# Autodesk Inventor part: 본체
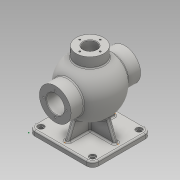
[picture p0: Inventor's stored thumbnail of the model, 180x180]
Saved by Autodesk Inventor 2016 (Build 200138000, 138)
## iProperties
Created: 2017-01
Part Number: 본체
Material: 일반
Document SubType Name: Modeling
Designer: Administrator
Density: 1 g/cm^3
Appearance: 기본값
Author: Administrator
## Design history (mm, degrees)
sketch "스케치1"
  geometry: L1 (0, 0)-(125, 0); L2 (125, 0)-(125, 115); L3 (125, 115)-(0, 115); L4 (0, 115)-(0, 0)
  constraints: 8 end point, 2 parallel, 1 horizontal, 1 perpendicular
  dimensions: "d0" = 125 distance between parallel lines of L2 L4; "d1" = 115 distance between parallel lines of L1 L3
extrude "돌출1" new body sketch "스케치1" distance "d2" = 10; taper "d3" = 0 deg
fillet "모깎기1" dims "d4" = 12
sketch "스케치2"
  geometry: A1 r 12 centre (12, 103) between (12, 115) and (0, 103) reference; A2 r 12 centre (113, 103) between (125, 103) and (113, 115) reference; A3 r 12 centre (113, 12) between (113, 0) and (125, 12) reference; A4 r 12 centre (12, 12) between (0, 12) and (12, 0) reference; 5 further points
  constraints: 4 coincident
hole "구멍1" sketch "스케치2" at (12, 103), (113, 103), (113, 12), (12, 12) diameter "d5" = 8; stored, may be unused: countersink angle "d9" = 90 deg, drill point angle "d11" = 118 deg; dims "d6" = 6, "d7" = 12, "d8" = 3, "d10" = 8
node "작업 평면2"
sketch "스케치5"
  geometry: L1 (0, 91)-(0, 0) reference; L2 (0, 45.5)-(-120.31, 45.5); L3 (-85, -22.5)-(-85, 113.5); L4 (-85, -22.5)-(-116, -22.5); L5 (-116, -22.5)-(-116, 2.512); L6 (-116, 88.488)-(-116, 113.5); L7 (-116, 113.5)-(-85, 113.5); A1 r 53 centre (-85, 45.5) between (-116, 88.488) and (-116, 2.512); 1 further point
  constraints: 12 end point, 2 horizontal, 2 midpoint, 2 perpendicular, 2 point on circle, 2 vertical, 1 centre point, 1 point on line
  dimensions: "d31" = 106 diameter of A1; "d32" = 85 distance between parallel lines of L1 L3; "d33" = 31 distance between parallel lines of L3 L5; "d34" = 31 distance between parallel lines of L3 L6; "d35" = 136 distance between parallel lines of L7 L4; "d36" = 68 distance between parallel lines of L4 L2
revolve "회전2" sketch "스케치5" stored, may be unused: angle "d37" = 90 deg
sketch "스케치6"
  geometry: L1 (-54, -22.5)-(-116, -22.5) reference; L2 (-85, -22.5)-(-85, 113.5); L3 (-54, 113.5)-(-116, 113.5) reference; L4 (-85, -22.5)-(-102.5, -22.5); L5 (-102.5, -22.5)-(-102.5, 6.222); L6 (-85, 113.5)-(-102.5, 113.5); L7 (-102.5, 95.75)-(-103.5, 95.75); L8 (-103.5, 95.75)-(-103.5, 97.5); L9 (-103.5, 97.5)-(-102.5, 97.5); L10 (-102.5, 84.778)-(-102.5, 95.75); L11 (-102.5, 97.5)-(-102.5, 113.5); A1 r 43 centre (-85, 45.5) between (-102.5, 84.778) and (-102.5, 6.222); 1 further point
  constraints: 18 end point, 3 midpoint, 3 perpendicular, 3 point on line, 2 parallel, 2 point on circle, 1 centre point, 1 vertical
  dimensions: "d38" = 86 diameter of A1; "d39" = 17.5 distance between parallel lines of L2 L5; "d40" = 17.5 distance between parallel lines of L2 L10; "d41" = 16 distance between parallel lines of L3 L9; "d42" = 1.75 distance between parallel lines of L7 L9; "d43" = 18.5 distance between parallel lines of L2 L8
revolve "회전3" sketch "스케치6" stored, may be unused: angle "d44" = 90 deg
sketch "스케치7"
  geometry: C1 r 17.5 at (0, 0) reference; A1 r 22.5 centre (0, 0) between (0, 22.5) and (22.5, 0); 3 further points
  constraints: 4 point on circle, 1 centre point, 1 coincident
  dimensions: "d45" = 45 diameter of A1
hole "구멍2" sketch "스케치7" at (0, 22.5), (22.5, 0), (0, -22.5), (-22.5, 0) diameter "d46" = 3.242; stored, may be unused: countersink angle "d50" = 90 deg, drill point angle "d52" = 118 deg; dims "d47" = 12, "d48" = 12, "d49" = 3, "d51" = 15
sketch "스케치8"
  geometry: C1 r 17.5 at (0, 0) reference; A1 r 24 centre (0, 0) between (-24, 0) and (0, -24); 3 further points
  constraints: 4 point on circle, 1 centre point, 1 coincident
  dimensions: "d53" = 48 diameter of A1
hole "구멍3" sketch "스케치8" at (-24, 0), (0, -24), (24, 0), (0, 24) diameter "d54" = 3.242; stored, may be unused: countersink angle "d58" = 90 deg, drill point angle "d60" = 118 deg; dims "d55" = 16, "d56" = 12, "d57" = 3, "d59" = 19
node "작업 평면3"
sketch "스케치9"
  geometry: L1 (-31.5, -10.5)-(-93.5, -10.5) reference; L2 (-62.5, -10.5)-(-62.5, 125.5); L3 (-31.5, 125.5)-(-93.5, 125.5) reference; L4 (0, 103)-(0, 12) reference; L5 (0, 57.5)-(-125, 57.5); L6 (-125, 12)-(-125, 103) reference; C1 r 27 at (-62.5, 57.5); 1 further point
  constraints: 4 end point, 4 midpoint, 1 centre point
  dimensions: "d62" = 54 diameter of C1; "d63" = 0 distance from line of C1.centre L2; "d64" = 0 distance from line of L5 C1.centre
extrude "돌출2" join sketch "스케치9" stored distance "d65" = 10; taper "d66" = 0 deg
sketch "스케치10"
  geometry: C1 r 27 at (0, 0) reference; C2 r 13 at (0, 0); 1 further point
  constraints: 1 centre point, 1 coincident
  dimensions: "d67" = 26 diameter of C2
extrude "돌출3" cut sketch "스케치10" distance "d68" = 60.25; taper "d69" = 0 deg
sketch "스케치11"
  geometry: C1 r 13 at (0, 0) reference; A1 r 20 centre (0, 0) between (0, 20) and (20, 0); 3 further points
  constraints: 4 point on circle, 1 centre point, 1 coincident
  dimensions: "d70" = 40 diameter of A1
hole "구멍4" sketch "스케치11" at (0, 20), (20, 0), (0, -20), (-20, 0) diameter "d71" = 3.242; stored, may be unused: countersink angle "d75" = 90 deg, drill point angle "d77" = 118 deg; dims "d72" = 9, "d73" = 12, "d74" = 3, "d76" = 11
sketch "스케치12"
  geometry: L1 (-10, 91)-(-10, 0) reference; L2 (-85.332, 45.09)-(-10, 45.5); L3 (-44.107, 11.78)-(-10, -2); L4 (-44.613, 79.016)-(-10, 93); L5 (-10, -12)-(-10, 0) reference; L6 (-10, 91)-(-10, 103) reference; L7 (-10, -12)-(-10, 103); L8 (-10, 103)-(0, 103) reference; L9 (0, -12)-(-10, -12) reference; L10 (-10, -2)-(-10, 93); A1 r 53 centre (-85.332, 45.09) between (-44.107, 11.78) and (-44.613, 79.016); A2 r 53 centre (-85.332, 45.09) between (-44.107, 11.78) and (-44.613, 79.016)
  constraints: 10 end point, 4 point on circle, 2 centre point, 2 coincident, 2 point on line, 1 collinear, 1 midpoint, 1 vertical
  dimensions: "d79" = 10 distance from line of L8 L4.end; "d80" = 10 distance from line of L9 L3.end; "d81" = 112 deg angle of L5 L3; "d82" = 112 deg angle of L4 L6; "d84" = 106 diameter of A2
extrude "돌출4" join sketch "스케치12" stored distance "d85" = 8; taper "d86" = 0 deg
node "작업 평면4"
sketch "스케치13" dims "d88" = 106
  geometry: L1 (13.121, 47.426)-(-2, 10); L2 (0, 10)-(0, 0) reference; L3 (95, 10)-(107, 10) reference; L4 (0, 10)-(107, 10); L5 (-12, 0)-(-12, 10) reference; L6 (-12, 10)-(0, 10) reference; C1 r 17.5 at (50.5, 85) reference; 1 further point
  constraints: 4 end point, 1 coincident, 1 horizontal, 1 point on line, 3 other
  dimensions: "d89" = 10 distance from line of L5 L1.end; "d90" = 112 deg angle of L6 L1
feature "리브1" sketch "스케치13" dims "d91" = 1, "d92" = 8, "d93" = 0, "d94" = 0, "d95" = 1, "d96" = 1
sketch "스케치14" dims "d97" = 106
  geometry: L1 (103, 10)-(87.879, 47.426); L2 (46.5, 10)-(54.5, 10) reference; L3 (101, 10)-(113, 10) reference; L4 (54.5, 10)-(113, 10); L5 (113, 10)-(113, 0) reference; C1 r 17.5 at (50.5, 85) reference; 2 further points
  constraints: 4 end point, 1 coincident, 1 collinear, 1 point on line, 3 other
  dimensions: "d98" = 10 distance from line of L5 L1.start; "d99" = 112 deg angle of L1 L3
feature "리브2" sketch "스케치14" dims "d100" = 1, "d101" = 8, "d102" = 0, "d103" = 0, "d104" = 1, "d105" = 1
fillet "모깎기2" dims "d106" = 3
fillet "모깎기3" dims "d107" = 3
chamfer "모따기1" distance "d108" = 1; stored, may be unused: second distance "d109" = 2, angle "d110" = 45 deg
sketch "스케치15"
  geometry: 1 further point
node "작업 평면5"
sketch "스케치16"
  geometry: L1 (136.006, 59.067)-(136.006, 31.933); L2 (136.006, 31.933)-(143.994, 31.933); L3 (143.994, 31.933)-(143.994, 59.067); L4 (143.994, 59.067)-(136.006, 59.067); L5 (150, 18.5)-(150, 72.5) reference; L6 (116, 113.5)-(54, 113.5) reference; 3 further points
  constraints: 2 midpoint, 2 other
  dimensions: "d112" = 10 distance from line of L5 point (140, 31.933); "d113" = 68 distance from line of L6 point (143.994, 45.5)
feature "엠보싱1" sketch "스케치16" dims "d0" = 125, "d1" = 115, "d7" = 12, "d114" = 0.5, "d115" = 0
node "솔리드1"
other parameters: "d30" = -62.5, "d87" = -57.5, "d111" = 16.75
